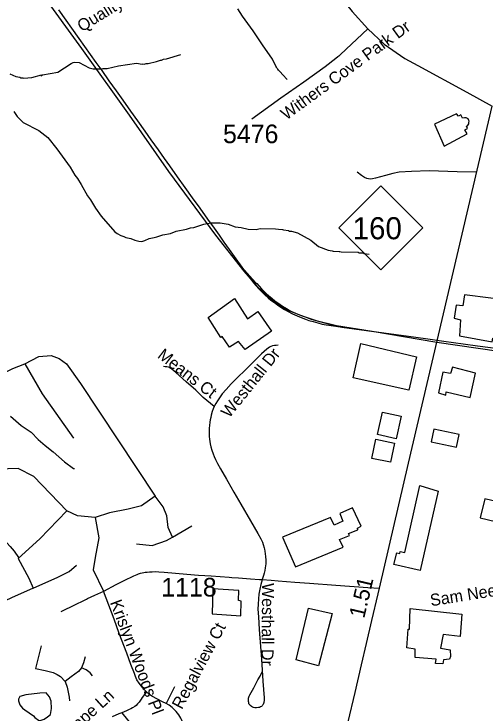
# Model space of a CAD drawing. Extents: x 1383679 to 1536984, y 460658 to 651027.
# Drawn here: x 1404948 to 1408689, y 505648 to 511196 of the extents above; entities that cross this region are included whole.
import ezdxf

# ---------------------------------------------------------------- set-up
doc = ezdxf.new("R2010")
doc.units = 0
for name, color, linetype in [('Exist Cultural Warehouse Building Footprint', 7, 'Continuous'), ('Exist Hydrographic Misc Water Feature', 7, 'Continuous'), ('Exist Railroad Mainline', 7, 'Continuous'), ('Exist Railroad Spur', 7, 'Continuous'), ('Exist Road Non-System Secondary Historical Number Label', 7, 'Continuous'), ('Exist Road Non-System Type 51', 7, 'Continuous'), ('Exist Road Non-System Type 51 Label', 7, 'Continuous'), ('Exist Road Primary NC Attributed', 7, 'Continuous'), ('Exist Road Primary NC Service Mileage Hundredths English Label', 7, 'Continuous'), ('Exist Road Primary NC Shield CELL', 7, 'Continuous'), ('Exist Road Primary NC Shield Number Label', 7, 'Continuous'), ('Exist Road Secondary Type 51 Attributed', 7, 'Continuous')]:
    doc.layers.add(name, color=color, linetype=linetype)

msp = doc.modelspace()

# ---------------------------------------------------------------- linework, layer by layer
at = {"layer": 'Exist Cultural Warehouse Building Footprint'}
for points in [[(1408454.2, 510405.9), (1408281.2, 510322), (1408356, 510147.3), (1408538.4, 510247.1), (1408522, 510278.9), (1408541.9, 510289.4), (1408533.7, 510306.1), (1408543.1, 510310.7), (1408552.4, 510326.8), (1408553.6, 510331.4), (1408553, 510335.9), (1408554.2, 510346.1), (1408553, 510352.9), (1408546, 510364.8), (1408531.4, 510372.2), (1408517.9, 510372.2), (1408502.2, 510369.4), (1408488.7, 510396), (1408470.6, 510385.5), (1408454.2, 510405.9)], [(1408518.4, 508970.8), (1408505.9, 508882.7), (1408452.6, 508887.2), (1408436.9, 508785.4), (1408487.1, 508771.7), (1408477.7, 508645.5), (1408737.8, 508598.4), (1408742.5, 508625.7), (1408894.5, 508606), (1408936.8, 508917.6), (1408518.4, 508970.8)], [(1406486.3, 508790.7), (1406694.4, 508940.4), (1406797.3, 508779.3), (1406881.5, 508838.3), (1406989.1, 508681.8), (1406781, 508536.6), (1406727.2, 508600.1), (1406657, 508554.7), (1406598.6, 508640.9), (1406586.9, 508631.8), (1406486.3, 508790.7)], [(1408137.6, 508479), (1408076.5, 508214.5), (1407634.6, 508311.8), (1407697.3, 508583.9), (1408137.6, 508479)], [(1408347.6, 508358.2), (1408311.6, 508192.5), (1408371.1, 508175.8), (1408372.7, 508201.6), (1408563.9, 508156), (1408604.6, 508350.6), (1408422.8, 508396.2), (1408407.2, 508347.5), (1408347.6, 508358.2)], [(1407868.1, 508041.2), (1408015.4, 508008.9), (1407976.2, 507829.9), (1407828.9, 507862.2), (1407868.1, 508041.2)], [(1408275.5, 507904.4), (1408254.7, 507805.2), (1408455.7, 507763), (1408476.5, 507862.2), (1408275.5, 507904.4)], [(1407814.8, 507826.9), (1407962.7, 507796), (1407930.8, 507642.9), (1407782.9, 507673.8), (1407814.8, 507826.9)], [(1408164.3, 507459.7), (1408310, 507415.6), (1408165.8, 506786.3), (1407959, 506831.9), (1407980.9, 506926.1), (1408006, 506921.6), (1408009.1, 506935.2), (1408045.2, 506929.2), (1408164.3, 507459.7)], [(1408678.3, 507354.1), (1408642.2, 507203.6), (1408950.9, 507129.1), (1408988.5, 507279.6), (1408678.3, 507354.1)], [(1407075.1, 507050.8), (1407180.1, 506815.1), (1407556.2, 506970.2), (1407528, 507032.5), (1407607.9, 507062.9), (1407600.1, 507078.1), (1407672.2, 507108.5), (1407669, 507120.7), (1407700.4, 507137.4), (1407631.4, 507281.8), (1407529.6, 507236.2), (1407554.7, 507175.4), (1407485.7, 507145), (1407455.9, 507205.8), (1407075.1, 507050.8)], [(1406525.1, 506641.1), (1406518.8, 506443.4), (1406744.5, 506425.2), (1406747.6, 506543.8), (1406727.2, 506546.8), (1406730.4, 506627.4), (1406525.1, 506641.1)], [(1407281.9, 506488), (1407469, 506446.1), (1407362.5, 506029.9), (1407184, 506077.4), (1407281.9, 506488)], [(1408088.1, 506485.2), (1408496.9, 506440.5), (1408482.5, 506261.7), (1408350.1, 506278.5), (1408327, 506169.6), (1408404.8, 506155.6), (1408407.6, 506105.3), (1408399, 506083), (1408352.9, 506077.4), (1408347.2, 506046.7), (1408289.6, 506049.5), (1408292.5, 506083), (1408128.4, 506096.9), (1408128.4, 506161.2), (1408062.1, 506172.4), (1408070.8, 506320.4), (1408082.3, 506320.4), (1408088.1, 506485.2)]]:
    msp.add_lwpolyline(points, dxfattribs=at)
at = {"layer": 'Exist Hydrographic Misc Water Feature'}
for points in [[(1404914.2, 510720.8), (1404961.8, 510699.7), (1404993.7, 510695), (1405001.6, 510690.9), (1405017.6, 510690.5), (1405025.6, 510686.3), (1405089.7, 510692.9), (1405166.9, 510714.5), (1405162.1, 510707.2), (1405174.1, 510715), (1405294.7, 510736.2), (1405400.2, 510803.9), (1405416.3, 510811.5), (1405428.4, 510813.2), (1405464.4, 510812.4), (1405543.4, 510770.6), (1405575.3, 510761.9), (1405647.3, 510760.3), (1405655.4, 510764.1), (1405687.4, 510763.4), (1405777.6, 510785.1), (1405920.3, 510806.2), (1405964.1, 510797.2), (1405972.2, 510801), (1405980.2, 510798.8), (1405996.3, 510804.5), (1406012.3, 510804.1), (1406076.7, 510818.6), (1406108.9, 510829.9), (1406116.9, 510829.7), (1406133.1, 510837.4), (1406157.2, 510840.8), (1406269.8, 510874.3)], [(1404945.8, 510424.3), (1404973, 510383.7), (1405022, 510336.5), (1405144.6, 510271.9), (1405215.4, 510216.3), (1405287.5, 510128.7), (1405392.3, 509982.4), (1405431, 509917.6), (1405450.5, 509893.1), (1405481.4, 509844.5), (1405531.5, 509755.4), (1405554.7, 509722.9), (1405593.4, 509658), (1405639.9, 509593), (1405747.4, 509470.7), (1405765, 509456.3), (1405794.6, 509439.6), (1405818.5, 509433), (1405834.3, 509424.7), (1405874.2, 509415.8), (1405905.9, 509403.1), (1405937.8, 509394.4), (1405961.8, 509393.9), (1405985.8, 509401.3), (1406018.2, 509416.6), (1406058.3, 509423.7), (1406079, 509430.4)], [(1406079, 509430.4), (1406126.9, 509446.1), (1406187.1, 509456.8), (1406234, 509475.2), (1406315.9, 509489.8), (1406348.2, 509501.1), (1406372.2, 509504.6), (1406452.8, 509530.7), (1406507, 509541.5), (1406581, 509539.9), (1406644.8, 509530.4), (1406700.4, 509509.2), (1406748.2, 509504.1), (1406804, 509490.9), (1406868, 509489.4), (1406900.2, 509496.7), (1407020.1, 509494), (1407044, 509489.5), (1407076, 509488.8), (1407083.9, 509484.6), (1407123.8, 509479.7), (1407131.8, 509475.5), (1407147.8, 509475.2), (1407195.5, 509462.1), (1407300.4, 509403.8), (1407361.1, 509354.4), (1407436.5, 509324.7), (1407468.5, 509320), (1407476.4, 509315.8), (1407524.3, 509312.8), (1407530.3, 509314.6), (1407540.2, 509310.4), (1407676.2, 509307.3), (1407684.1, 509303.2), (1407716.1, 509302.5), (1407724.1, 509298.3), (1407763.9, 509291.4)], [(1404919.5, 508007.9), (1405005.9, 507934), (1405085.1, 507882.5), (1405139.5, 507825), (1405194.5, 507775.8), (1405259.5, 507726.4), (1405347.7, 507646.4), (1405418.6, 507594.8), (1405426.6, 507594.7)], [(1405236.6, 505643.1), (1405245.5, 505691.3), (1405242.6, 505748.8), (1405229.4, 505785.2), (1405201.9, 505816.1), (1405153.8, 505814.6), (1405041.6, 505801.3), (1404995.2, 505788.3), (1404984.9, 505766.3), (1404984.6, 505752.4), (1404994, 505720.2), (1405015.4, 505695.1), (1405033.2, 505680.8), (1405102.3, 505633.5), (1405114.1, 505619.3), (1405141.8, 505599.1), (1405155.7, 505597.1), (1405187.9, 505608), (1405214.2, 505625.5), (1405236.6, 505643.1)]]:
    msp.add_lwpolyline(points, dxfattribs=at)
at = {"layer": 'Exist Railroad Mainline'}
for points in [[(1405300.4, 511227.8), (1405461.2, 511001.5), (1405597.9, 510810.6), (1405643, 510747.5), (1405700.3, 510666.9), (1405757.7, 510586), (1405809.7, 510513.4), (1405872.5, 510425.6), (1405926.4, 510348.9), (1405984.2, 510267.9), (1406032.8, 510199.2), (1406090.3, 510118.8), (1406139.1, 510050.6), (1406181.3, 509992.1), (1406241.9, 509906.2), (1406302.6, 509821.4), (1406360.7, 509739.5), (1406420.6, 509656.4), (1406481.6, 509569.9), (1406533.2, 509497.5), (1406572.9, 509443.4), (1406611.8, 509387.9), (1406653.9, 509328.8), (1406693.4, 509273.1), (1406753.5, 509188.8)], [(1406753.5, 509188.8), (1406795, 509132.3), (1406831.2, 509085.3), (1406847.1, 509066), (1406864.2, 509045.2), (1406892.1, 509015.1), (1406917.7, 508988.9), (1406938.8, 508967.4), (1406962.1, 508947.4), (1406984.8, 508928.9), (1407011.3, 508908.8), (1407038.3, 508889.1), (1407062.1, 508873), (1407091.1, 508854.7), (1407121.5, 508837.6), (1407155.5, 508820.2), (1407191.2, 508803.3), (1407222.9, 508790.5), (1407257.4, 508777.8), (1407285.7, 508767.8), (1407317.8, 508758.2), (1407355, 508747.7), (1407390.8, 508739), (1407423, 508732.9), (1407462.1, 508726.9), (1407534.2, 508716.7)], [(1407534.2, 508716.7), (1407546.9, 508714.9), (1408075, 508641.5), (1408209.8, 508624.1), (1408355.7, 508603.6), (1408506.9, 508582), (1408619.9, 508566.4), (1408724.7, 508551.7), (1408759.1, 508546.4)]]:
    msp.add_lwpolyline(points, dxfattribs=at)
at = {"layer": 'Exist Railroad Spur'}
msp.add_lwpolyline([(1406753.5, 509188.8), (1406816.8, 509117.6), (1406865.8, 509066), (1406871.8, 509059.7), (1406909.7, 509019), (1406944.8, 508982.7), (1406967, 508961.4), (1406990.7, 508942.9), (1407016, 508922.9), (1407046.1, 508901.4), (1407076.9, 508879.9), (1407108.9, 508860.8), (1407143, 508841.9), (1407180, 508824.2), (1407217.8, 508808.9), (1407254.3, 508794.8), (1407294.1, 508781.2), (1407339.5, 508766.3), (1407380.4, 508755.1), (1407436.7, 508740.3), (1407534.2, 508716.7)], dxfattribs=at)
at = {"layer": 'Exist Road Non-System Type 51'}
for p, q in [((1406204.8, 507049.8), (1406356.2, 507139)), ((1405164.2, 506188), (1405119.1, 506009.9)), ((1406221, 505863.9), (1406152.9, 505730.6))]:
    msp.add_line(p, q, dxfattribs=at)
for points in [[(1405175.3, 511350.2), (1405482.1, 510922), (1405861.3, 510393.5), (1406171.6, 509948.6), (1406543.9, 509443.5), (1406768.8, 509159), (1406871.1, 509042.9), (1406970.2, 508946.8), (1407054.4, 508886.7), (1407117.9, 508849.9), (1407231.8, 508802.6), (1407343.2, 508765.8), (1407504.2, 508726.5), (1407785.6, 508681.7), (1408297.7, 508594)], [(1407112.3, 510677.8), (1407078.9, 510713.8), (1407056.7, 510737.4), (1407052.6, 510742.2), (1407045.5, 510750.1), (1407039.6, 510757.5), (1407033.9, 510764.8), (1407030.8, 510770.1), (1407028.2, 510774.4), (1407023.3, 510782.8), (1407016.5, 510795.6), (1407000, 510829.2), (1406995.8, 510836.8), (1406990.6, 510846.2), (1406921.7, 510945), (1406844.5, 511061.3), (1406757.9, 511179.2), (1406720.8, 511236.7)], [(1407752.7, 511078), (1407536.3, 510874.9), (1407522.8, 510863.1), (1407513.9, 510855.7), (1407498.3, 510843.3), (1407414.6, 510777.8), (1407244.4, 510655.8), (1407061.8, 510528), (1406832.3, 510362.5)], [(1408616.6, 509942.1), (1408459.1, 509946.1), (1408238.7, 509952.5), (1408099.2, 509948.5), (1408001, 509942.1), (1407949, 509931.7), (1407892.1, 509917.3), (1407812, 509895.7), (1407788.1, 509889.3), (1407771.6, 509887.7), (1407743.5, 509892.5), (1407725.4, 509900.5), (1407703.1, 509917.3), (1407668.4, 509943.7)], [(1407041.8, 508570.6), (1407024.5, 508569.6), (1407011.3, 508568.5), (1406997.4, 508565.8), (1406984.4, 508561.2), (1406971.7, 508554.4), (1406951.4, 508540.4), (1406910.5, 508502.8), (1406873.1, 508464.7), (1406834.3, 508428), (1406800.9, 508394.8), (1406763.4, 508356.7), (1406736.2, 508330.3), (1406699, 508294.3), (1406669.3, 508265.2), (1406629.4, 508221.2), (1406598.7, 508184.6), (1406560, 508130.5), (1406546.6, 508109.3), (1406536.7, 508091), (1406534.6, 508085.9)], [(1408297.7, 508594), (1408953.6, 508500.2)], [(1405033.6, 508422.4), (1405145, 508480.3), (1405242.9, 508489.3), (1405305.3, 508467), (1405363.1, 508422.4), (1405474.5, 508266.4), (1406066.7, 507375.1)], [(1404811, 508324.4), (1404940.1, 508386.8), (1405033.6, 508422.4)], [(1405033.6, 508422.4), (1405171.7, 508186.2), (1405421, 507834.2)], [(1406534.6, 508085.9), (1406448.5, 508157.6), (1406388.3, 508213.5), (1406313.4, 508280.9), (1406231.5, 508356), (1406199.3, 508381.3), (1406191.2, 508387), (1406186, 508390.1), (1406180.1, 508393.2), (1406171.3, 508396.8), (1406159.3, 508400.2), (1406146.9, 508401), (1406133.1, 508401.3)], [(1406534.6, 508085.9), (1406526.3, 508066.3), (1406519.6, 508047), (1406511.4, 508017), (1406507.4, 507997.5), (1406504, 507979.5), (1406500.6, 507959.9), (1406497.2, 507933.8), (1406495.4, 507913.7), (1406494.7, 507896.7), (1406495, 507880.1), (1406495, 507874.7), (1406496, 507846.3), (1406496.9, 507827.5), (1406499.2, 507807.5), (1406502.7, 507788.2), (1406507.9, 507765.3), (1406515.3, 507739.2), (1406526, 507709.2), (1406534.2, 507689), (1406544.5, 507665.5), (1406560.5, 507633.2), (1406584.9, 507591.1), (1406631.8, 507508.9), (1406643.1, 507489.7), (1406690.4, 507406.2), (1406746.9, 507311.4), (1406823.4, 507179.9), (1406880.7, 507080), (1406904.6, 507036.8), (1406916.2, 507009.9), (1406923.4, 506990.6), (1406931, 506966.3), (1406933.5, 506954.1), (1406936.6, 506938.2), (1406939.3, 506917.4), (1406941.4, 506895.8), (1406942.9, 506867.1), (1406942.9, 506838.5), (1406939.4, 506807.8), (1406935.6, 506786.8), (1406930.8, 506765.7), (1406925.5, 506746.8), (1406915.1, 506714)], [(1405367.6, 507259.3), (1405104.9, 507531.1), (1404980.2, 507593.5), (1404819.9, 507589.1), (1404646.2, 507477.6), (1404485.9, 507361.8), (1404392.4, 507308.3), (1404281.1, 507281.6), (1404183.1, 507281.6), (1404107.4, 507299.4), (1403982.7, 507330.6)], [(1406066.7, 507375.1), (1405959.8, 507299.4), (1405853, 507272.6), (1405706, 507241.5), (1405590.2, 507205.8)], [(1406204.8, 507049.8), (1406169.1, 507125.6), (1406160.2, 507219.2), (1406129.1, 507290.5), (1406066.7, 507375.1)], [(1405367.6, 507259.3), (1405153.9, 507036.5), (1404980.2, 506880.5)], [(1405590.2, 507205.8), (1405452.2, 507219.2), (1405367.6, 507259.3)], [(1405590.2, 507205.8), (1405621.4, 507045.4), (1405590.2, 506889.4), (1405576.9, 506791.3), (1405657.1, 506622)], [(1404814.9, 507074.5), (1404842, 507052.1), (1404890.6, 507005.8), (1404916.9, 506974.9), (1404949.2, 506939.4), (1404984.8, 506887.8)], [(1405919.8, 506996.3), (1406044.4, 506983), (1406155.8, 507023.1), (1406204.8, 507049.8)], [(1404980.2, 506880.5), (1405064.8, 506724.5), (1405100.4, 506644.3)], [(1405100.4, 506644.3), (1405296.4, 506733.4), (1405385.4, 506778), (1405443.3, 506827)], [(1405660.4, 506622.7), (1405756.6, 506673.6), (1405820.9, 506705.4), (1405896.9, 506742.8), (1405924, 506754.5), (1405935.9, 506759.2), (1405950.8, 506763.4), (1405962.8, 506766.8), (1405976.1, 506769.5), (1405988.2, 506771.5), (1406003.1, 506773), (1406023, 506775), (1406043.2, 506776.1), (1406067.8, 506776.5), (1406097.1, 506775.7), (1406138.9, 506772.5), (1406227.6, 506764.7), (1406317, 506757), (1406409, 506749.5), (1406511, 506742.1), (1406653.1, 506731.8), (1406675.4, 506729.9), (1406726.1, 506726.3), (1406822.4, 506720.2), (1406893.9, 506715.2), (1406915.1, 506714)], [(1406915.1, 506714), (1406914.2, 506711.3), (1406904.2, 506675.9), (1406895.1, 506636.5), (1406889.6, 506599.1), (1406885.2, 506560.9), (1406882.6, 506519.4), (1406881.3, 506480.1), (1406884.9, 506418.5), (1406890.6, 506317.6), (1406908.3, 506082), (1406921.4, 505909.2), (1406931.1, 505776.7), (1406930.7, 505757.6), (1406928.4, 505738.9), (1406926.5, 505731.4), (1406921.7, 505723.2), (1406917.7, 505717.8), (1406914, 505713.2), (1406908.5, 505708.5), (1406902.9, 505704.7), (1406893.6, 505700.5), (1406886.5, 505698.9), (1406870.6, 505697.2), (1406856.9, 505697.9), (1406846.2, 505699.9), (1406839, 505702.4), (1406831.2, 505706.8), (1406824.6, 505711.8), (1406817.8, 505717.8), (1406814, 505722.5), (1406810.3, 505730.1), (1406808.1, 505738.3), (1406806.6, 505747.2), (1406805.9, 505755.9), (1406806.2, 505764.8), (1406807, 505773.9), (1406809, 505781.4), (1406812.3, 505790), (1406816.5, 505799.8), (1406847.9, 505856.9), (1406881.5, 505918.5), (1406898.2, 505947.7), (1406915.3, 505982)], [(1406915.1, 506714), (1406986.1, 506709.9), (1407042.9, 506702.8), (1407174.8, 506693.9), (1407288.9, 506686.5), (1407497.5, 506670.5), (1407752.9, 506650.9), (1407845.1, 506646.6)], [(1405100.4, 506644.3), (1404929, 506569.7), (1404826.6, 506520.7)], [(1405523, 506559.1), (1405531.8, 506563.2), (1405588.9, 506589.8), (1405660.4, 506622.7)], [(1405997.3, 505825), (1405981.3, 505839.4), (1405957.4, 505867.7), (1405939.9, 505892.8), (1405922.9, 505919.9), (1405916.2, 505933.6), (1405910.9, 505945.5), (1405902.1, 505968.4), (1405875.3, 506040.5), (1405841.7, 506130), (1405782.4, 506287.2), (1405741.9, 506400.4), (1405657.1, 506622)], [(1405321, 506461.2), (1405436.2, 506516.2), (1405500.6, 506548.8), (1405523, 506559.1)], [(1405512.9, 506101.4), (1405497.9, 506053.8), (1405484.1, 506013.7)], [(1405119.1, 506009.9), (1405195.6, 505992.3), (1405258.4, 505976), (1405290.9, 505962.2), (1405316, 505944.7), (1405352.4, 505907)], [(1405484.1, 506013.7), (1405459, 505984.8), (1405401.6, 505943.4), (1405352.4, 505907)], [(1405569.4, 505949.7), (1405550.6, 505974.8), (1405520.4, 505997.3), (1405484.1, 506013.7)], [(1405352.4, 505907), (1405368.6, 505860.6), (1405378.8, 505820.5), (1405385, 505781.6), (1405388.8, 505752.8)], [(1405997.3, 505825), (1405964.7, 505778.3), (1405955.5, 505764.9), (1405939, 505742.5), (1405927.4, 505727.8), (1405917.1, 505716.9), (1405904.6, 505706.5), (1405887.6, 505696.1), (1405874.8, 505689.9), (1405861.6, 505683.6), (1405850.9, 505677.9), (1405839.2, 505673.1), (1405804, 505658.7)], [(1406152.9, 505730.6), (1406125.9, 505745.5), (1406079.6, 505768.2), (1406047, 505786.3), (1406025.9, 505800.7), (1405997.3, 505825)], [(1406385.2, 505277), (1406331, 505442.5), (1406294.9, 505556.6), (1406285, 505580.2), (1406275.6, 505603.5), (1406269.1, 505615.7), (1406261.5, 505629.1), (1406253.2, 505642), (1406243.9, 505653.6), (1406232.9, 505666.9), (1406220.3, 505680.9), (1406200.9, 505699.3), (1406177.2, 505717.2), (1406152.9, 505730.6)], [(1405804, 505658.7), (1405780.2, 505649.7), (1405725.4, 505626.9)], [(1405804, 505658.7), (1405848.5, 505602.6), (1405865.3, 505582.1), (1405884.7, 505559.7), (1405891.4, 505550.4), (1405899.8, 505539.2), (1405906.1, 505529.2), (1405912.5, 505518.3), (1405918.5, 505507.8), (1405923.1, 505496.5), (1405927.5, 505486), (1405933.4, 505471.4), (1405939, 505453.7), (1405944.3, 505437.8), (1405951.8, 505411.4), (1405978, 505329.2), (1405989, 505294.9)]]:
    msp.add_lwpolyline(points, dxfattribs=at)
at = {"layer": 'Exist Road Primary NC Attributed'}
msp.add_lwpolyline([(1407595.2, 505585.5), (1407650.5, 505818), (1407701.8, 506037.6), (1407741.6, 506205.9), (1407784.6, 506389.5), (1407834.5, 506600.8), (1407845.1, 506646.6), (1408075.2, 507636.1), (1408736.5, 510466.6)], dxfattribs=at)
at = {"layer": 'Exist Road Primary NC Shield CELL'}
msp.add_lwpolyline([(1407522.2, 509500.4), (1407855.2, 509833.4), (1408188.2, 509500.4), (1407855.2, 509167.4)], close=True, dxfattribs=at)
at = {"layer": 'Exist Road Secondary Type 51 Attributed'}
msp.add_lwpolyline([(1404961.5, 515533.5), (1405081.1, 515357.9), (1405565, 514562.6), (1405783.8, 514231.4), (1406041.9, 513793.7), (1407003.6, 512208.3), (1407241.4, 511803), (1407528.8, 511343.2), (1407627.4, 511215.9), (1407752.7, 511078), (1407881.9, 510956.9), (1408044.5, 510842.8), (1408147.1, 510786.7), (1408535.7, 510576), (1408736.5, 510466.6)], dxfattribs=at)

# ---------------------------------------------------------------- texts
at = {"layer": 'Exist Road Non-System Secondary Historical Number Label'}
for s, p in [('5476', (1406604.4, 510172.4)), ('1118', (1406115, 506579.5))]:
    msp.add_text(s, height=147.64, dxfattribs=at).set_placement(p)
at = {"layer": 'Exist Road Non-System Type 51 Label'}
for s, rotation, p in [('Quality Dr', 31.7336, (1405486.4, 511050.4)), ('Withers Cove Park Dr', 36.089, (1407106.2, 510351.3)), ('Means Ct', 322.3576, (1406078.5, 508477.3)), ('Westhall Dr', 51.2712, (1406653.7, 507988.5)), ('Westhall Dr', 269.5106, (1406914.5, 506686.8)), ('Sam Neely Rd', 8.9694, (1408253.6, 506502)), ('Krislyn Woods Pl', 290.7499, (1405707.3, 506532.7)), ('Regalview Ct', 61.9635, (1406278, 505678.8)), ('Seascape Ln', 42.2222, (1405200.6, 505283.8))]:
    msp.add_text(s, height=95, rotation=rotation, dxfattribs=at).set_placement(p)
at = {"layer": 'Exist Road Primary NC Service Mileage Hundredths English Label'}
msp.add_text('1.51', height=125, rotation=76.7258, dxfattribs=at).set_placement((1407723.1, 506400.9))
at = {"layer": 'Exist Road Primary NC Shield Number Label'}
msp.add_text('160', height=175, dxfattribs=at).set_placement((1407631.4, 509410.7))

doc.saveas('drawing.dxf')
